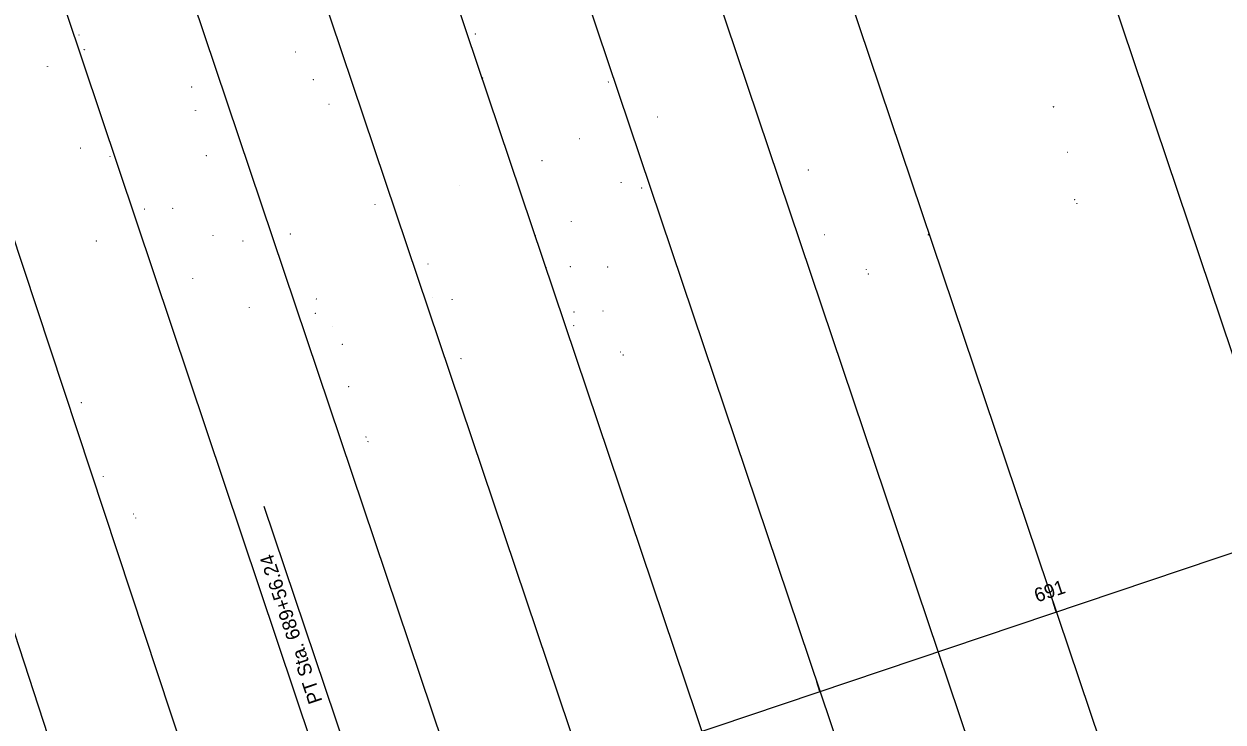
# Model space of a CAD drawing. Extents: x 2175772 to 2185556, y 721391 to 722853.
# Drawn here: x 2178626.6 to 2178867, y 721714.1 to 721854.1 of the extents above; entities that cross this region are included whole.
import ezdxf

# ---------------------------------------------------------------- set-up
doc = ezdxf.new("R2010")
doc.units = 0
for name, color, linetype in [('DT_X_Triangles', 7, 'Continuous'), ('RD_X_Cells', 7, 'Continuous'), ('SV_X_Shot_Marker', 7, 'Continuous'), ('SV_X_Text_Comment', 7, 'Continuous'), ('SV_X_Text_Description', 7, 'Continuous')]:
    doc.layers.add(name, color=color, linetype=linetype)

msp = doc.modelspace()

# ---------------------------------------------------------------- linework, layer by layer
at = {"layer": 'DT_X_Triangles'}
for p, q in [((2178697.33, 721690.31), (2180444.45, 722278.43)), ((2178697.01, 721691.26), (2178674.76, 721757.36)), ((2178833.58, 721736.18), (2178832.94, 721738.07)), ((2178786.19, 721720.22), (2178785.55, 721722.12))]:
    msp.add_line(p, q, dxfattribs=at)
at = {"layer": 'RD_X_Cells'}
for p, q in [((2178717.04, 721852.07), (2178717.1, 721852.13)), ((2178717.04, 721852.13), (2178717.1, 721852.07)), ((2178717.04, 721852.07), (2178717.1, 721852.13)), ((2178717.04, 721852.13), (2178717.1, 721852.07)), ((2178638.67, 721848.98), (2178638.74, 721849.05)), ((2178638.67, 721849.05), (2178638.74, 721848.98)), ((2178638.67, 721848.98), (2178638.74, 721849.05)), ((2178638.67, 721849.05), (2178638.74, 721848.98)), ((2178681.04, 721848.52), (2178681.1, 721848.58)), ((2178681.04, 721848.58), (2178681.1, 721848.52)), ((2178681.04, 721848.52), (2178681.1, 721848.58)), ((2178681.04, 721848.58), (2178681.1, 721848.52)), ((2178684.57, 721842.93), (2178684.64, 721843)), ((2178684.57, 721843), (2178684.64, 721842.93)), ((2178684.57, 721842.93), (2178684.64, 721843)), ((2178684.57, 721843), (2178684.64, 721842.93)), ((2178718.5, 721843.24), (2178718.57, 721843.31)), ((2178718.5, 721843.31), (2178718.57, 721843.24)), ((2178718.5, 721843.24), (2178718.57, 721843.31)), ((2178718.5, 721843.31), (2178718.57, 721843.24)), ((2178660.15, 721841.45), (2178660.22, 721841.52)), ((2178660.15, 721841.52), (2178660.22, 721841.45)), ((2178660.15, 721841.45), (2178660.22, 721841.52)), ((2178660.15, 721841.52), (2178660.22, 721841.45)), ((2178660.94, 721836.71), (2178661, 721836.78)), ((2178660.94, 721836.78), (2178661, 721836.71)), ((2178660.94, 721836.71), (2178661, 721836.78)), ((2178660.94, 721836.78), (2178661, 721836.71)), ((2178687.73, 721838.02), (2178687.8, 721838.08)), ((2178687.73, 721838.08), (2178687.8, 721838.02)), ((2178687.73, 721838.02), (2178687.8, 721838.08)), ((2178687.73, 721838.08), (2178687.8, 721838.02)), ((2178832.99, 721837.53), (2178833.06, 721837.6)), ((2178832.99, 721837.6), (2178833.06, 721837.53)), ((2178832.99, 721837.53), (2178833.06, 721837.6)), ((2178832.99, 721837.6), (2178833.06, 721837.53)), ((2178663.1, 721827.71), (2178663.17, 721827.77)), ((2178663.1, 721827.77), (2178663.17, 721827.71)), ((2178663.1, 721827.71), (2178663.17, 721827.77)), ((2178663.1, 721827.77), (2178663.17, 721827.71)), ((2178783.8, 721824.8), (2178783.87, 721824.87)), ((2178783.8, 721824.87), (2178783.87, 721824.8)), ((2178783.8, 721824.8), (2178783.87, 721824.87)), ((2178783.8, 721824.87), (2178783.87, 721824.8)), ((2178641.05, 721810.58), (2178641.12, 721810.65)), ((2178641.05, 721810.65), (2178641.12, 721810.58)), ((2178641.05, 721810.58), (2178641.12, 721810.65)), ((2178641.05, 721810.65), (2178641.12, 721810.58)), ((2178736.1, 721805.41), (2178736.17, 721805.48)), ((2178736.1, 721805.48), (2178736.17, 721805.41)), ((2178736.1, 721805.41), (2178736.17, 721805.48)), ((2178736.1, 721805.48), (2178736.17, 721805.41)), ((2178712.41, 721798.78), (2178712.47, 721798.85)), ((2178712.41, 721798.85), (2178712.47, 721798.78)), ((2178712.41, 721798.78), (2178712.47, 721798.85)), ((2178712.41, 721798.85), (2178712.47, 721798.78)), ((2178736.86, 721796.33), (2178736.93, 721796.4)), ((2178736.86, 721796.4), (2178736.93, 721796.33)), ((2178736.86, 721796.33), (2178736.93, 721796.4)), ((2178736.86, 721796.4), (2178736.93, 721796.33)), ((2178690.38, 721789.84), (2178690.44, 721789.91)), ((2178690.38, 721789.91), (2178690.44, 721789.84)), ((2178690.38, 721789.84), (2178690.44, 721789.91)), ((2178690.38, 721789.91), (2178690.44, 721789.84)), ((2178638.07, 721778.14), (2178638.14, 721778.21)), ((2178638.07, 721778.21), (2178638.14, 721778.14)), ((2178638.07, 721778.14), (2178638.14, 721778.21)), ((2178638.07, 721778.21), (2178638.14, 721778.14))]:
    msp.add_line(p, q, dxfattribs=at)
at = {"layer": 'SV_X_Shot_Marker'}
for points in [[(2178721.45, 722226), (2178912.87, 721657.35)], [(2178674.07, 722210.05), (2178865.48, 721641.4)], [(2178650.37, 722202.07), (2178841.79, 721633.43)], [(2178626.68, 722194.1), (2178818.1, 721625.45)], [(2178602.98, 722186.12), (2178794.4, 721617.47)], [(2178579.29, 722178.15), (2178770.71, 721609.5)], [(2178555.6, 722170.17), (2178747.01, 721601.52)], [(2178532.42, 722162.37), (2178723.22, 721593.52)], [(2178510.77, 722155.16), (2178699.08, 721585.48)], [(2178489.09, 722148.05), (2178674.91, 721577.55)]]:
    msp.add_lwpolyline(points, dxfattribs=at)
at = {"layer": 'SV_X_Text_Comment'}
for p, q in [((2178637.62, 721851.87), (2178637.58, 721851.91)), ((2178637.62, 721851.91), (2178637.58, 721851.87)), ((2178637.62, 721851.87), (2178637.58, 721851.91)), ((2178637.62, 721851.91), (2178637.58, 721851.87)), ((2178637.6, 721851.89), (2178637.6, 721851.89)), ((2178637.6, 721851.89), (2178637.6, 721851.89)), ((2178631.31, 721845.63), (2178631.27, 721845.66)), ((2178631.31, 721845.66), (2178631.27, 721845.63)), ((2178631.31, 721845.63), (2178631.27, 721845.66)), ((2178631.31, 721845.66), (2178631.27, 721845.63)), ((2178631.29, 721845.65), (2178631.29, 721845.65)), ((2178631.29, 721845.65), (2178631.29, 721845.65)), ((2178743.77, 721842.48), (2178743.72, 721842.49)), ((2178743.77, 721842.48), (2178743.72, 721842.49)), ((2178743.76, 721842.51), (2178743.74, 721842.46)), ((2178743.76, 721842.51), (2178743.74, 721842.46)), ((2178743.75, 721842.48), (2178743.75, 721842.48)), ((2178743.75, 721842.48), (2178743.75, 721842.48)), ((2178753.55, 721835.52), (2178753.59, 721835.5)), ((2178753.55, 721835.52), (2178753.59, 721835.5)), ((2178753.56, 721835.49), (2178753.58, 721835.53)), ((2178753.56, 721835.49), (2178753.58, 721835.53)), ((2178753.57, 721835.51), (2178753.57, 721835.51)), ((2178753.57, 721835.51), (2178753.57, 721835.51)), ((2178738.04, 721831.08), (2178738, 721831.1)), ((2178738.04, 721831.08), (2178738, 721831.1)), ((2178738.03, 721831.12), (2178738.01, 721831.07)), ((2178738.03, 721831.12), (2178738.01, 721831.07)), ((2178738.02, 721831.09), (2178738.02, 721831.09)), ((2178738.02, 721831.09), (2178738.02, 721831.09)), ((2178637.89, 721829.24), (2178637.86, 721829.21)), ((2178637.86, 721829.24), (2178637.89, 721829.21)), ((2178637.89, 721829.24), (2178637.86, 721829.21)), ((2178637.86, 721829.24), (2178637.89, 721829.21)), ((2178637.88, 721829.23), (2178637.88, 721829.23)), ((2178637.88, 721829.23), (2178637.88, 721829.23)), ((2178643.83, 721827.49), (2178643.86, 721827.53)), ((2178643.86, 721827.5), (2178643.83, 721827.53)), ((2178643.83, 721827.49), (2178643.86, 721827.53)), ((2178643.86, 721827.5), (2178643.83, 721827.53)), ((2178643.84, 721827.51), (2178643.84, 721827.51)), ((2178643.84, 721827.51), (2178643.84, 721827.51)), ((2178730.48, 721826.72), (2178730.44, 721826.7)), ((2178730.48, 721826.72), (2178730.44, 721826.7)), ((2178730.47, 721826.69), (2178730.45, 721826.73)), ((2178730.47, 721826.69), (2178730.45, 721826.73)), ((2178730.46, 721826.71), (2178730.46, 721826.71)), ((2178730.46, 721826.71), (2178730.46, 721826.71)), ((2178835.9, 721828.36), (2178835.86, 721828.35)), ((2178835.9, 721828.36), (2178835.86, 721828.35)), ((2178835.89, 721828.33), (2178835.87, 721828.38)), ((2178835.89, 721828.33), (2178835.87, 721828.38)), ((2178835.88, 721828.35), (2178835.88, 721828.35)), ((2178835.88, 721828.35), (2178835.88, 721828.35)), ((2178714.01, 721821.82), (2178713.96, 721821.8)), ((2178714.01, 721821.82), (2178713.96, 721821.8)), ((2178713.99, 721821.79), (2178713.98, 721821.83)), ((2178713.99, 721821.79), (2178713.98, 721821.83)), ((2178713.98, 721821.81), (2178713.98, 721821.81)), ((2178713.98, 721821.81), (2178713.98, 721821.81)), ((2178746.3, 721822.3), (2178746.33, 721822.27)), ((2178746.3, 721822.27), (2178746.34, 721822.3)), ((2178746.3, 721822.3), (2178746.33, 721822.27)), ((2178746.3, 721822.27), (2178746.34, 721822.3)), ((2178746.32, 721822.29), (2178746.32, 721822.29)), ((2178746.32, 721822.29), (2178746.32, 721822.29)), ((2178750.36, 721821.23), (2178750.41, 721821.23)), ((2178750.36, 721821.23), (2178750.41, 721821.23)), ((2178750.38, 721821.25), (2178750.38, 721821.2)), ((2178750.38, 721821.25), (2178750.38, 721821.2)), ((2178750.38, 721821.23), (2178750.38, 721821.23)), ((2178750.38, 721821.23), (2178750.38, 721821.23)), ((2178837.2, 721818.93), (2178837.25, 721818.94)), ((2178837.2, 721818.93), (2178837.25, 721818.94)), ((2178837.22, 721818.96), (2178837.23, 721818.91)), ((2178837.22, 721818.96), (2178837.23, 721818.91)), ((2178837.22, 721818.94), (2178837.22, 721818.94)), ((2178837.22, 721818.94), (2178837.22, 721818.94)), ((2178650.72, 721817), (2178650.69, 721816.96)), ((2178650.69, 721817), (2178650.72, 721816.96)), ((2178650.72, 721817), (2178650.69, 721816.96)), ((2178650.69, 721817), (2178650.72, 721816.96)), ((2178650.71, 721816.98), (2178650.71, 721816.98)), ((2178650.71, 721816.98), (2178650.71, 721816.98)), ((2178656.43, 721817.12), (2178656.39, 721817.15)), ((2178656.43, 721817.12), (2178656.39, 721817.15)), ((2178656.4, 721817.11), (2178656.43, 721817.15)), ((2178656.4, 721817.11), (2178656.43, 721817.15)), ((2178656.41, 721817.13), (2178656.41, 721817.13)), ((2178656.41, 721817.13), (2178656.41, 721817.13)), ((2178697.02, 721817.95), (2178696.97, 721817.94)), ((2178697.02, 721817.95), (2178696.97, 721817.94)), ((2178697, 721817.92), (2178696.99, 721817.97)), ((2178697, 721817.92), (2178696.99, 721817.97)), ((2178697, 721817.94), (2178697, 721817.94)), ((2178697, 721817.94), (2178697, 721817.94)), ((2178837.69, 721818.15), (2178837.73, 721818.17)), ((2178837.69, 721818.15), (2178837.73, 721818.17)), ((2178837.7, 721818.18), (2178837.72, 721818.14)), ((2178837.7, 721818.18), (2178837.72, 721818.14)), ((2178837.71, 721818.16), (2178837.71, 721818.16)), ((2178837.71, 721818.16), (2178837.71, 721818.16)), ((2178736.29, 721814.52), (2178736.33, 721814.54)), ((2178736.29, 721814.52), (2178736.33, 721814.54)), ((2178736.3, 721814.55), (2178736.32, 721814.51)), ((2178736.3, 721814.55), (2178736.32, 721814.51)), ((2178736.31, 721814.53), (2178736.31, 721814.53)), ((2178736.31, 721814.53), (2178736.31, 721814.53)), ((2178680, 721812), (2178679.95, 721811.98)), ((2178680, 721812), (2178679.95, 721811.98)), ((2178679.99, 721811.97), (2178679.97, 721812.01)), ((2178679.99, 721811.97), (2178679.97, 721812.01)), ((2178679.98, 721811.99), (2178679.98, 721811.99)), ((2178679.98, 721811.99), (2178679.98, 721811.99)), ((2178787.18, 721811.84), (2178787.13, 721811.82)), ((2178787.18, 721811.84), (2178787.13, 721811.82)), ((2178787.17, 721811.81), (2178787.15, 721811.86)), ((2178787.17, 721811.81), (2178787.15, 721811.86)), ((2178787.16, 721811.83), (2178787.16, 721811.83)), ((2178787.16, 721811.83), (2178787.16, 721811.83)), ((2178664.54, 721811.67), (2178664.49, 721811.68)), ((2178664.54, 721811.67), (2178664.49, 721811.68)), ((2178664.51, 721811.65), (2178664.52, 721811.7)), ((2178664.51, 721811.65), (2178664.52, 721811.7)), ((2178664.52, 721811.67), (2178664.52, 721811.67)), ((2178664.52, 721811.67), (2178664.52, 721811.67)), ((2178670.48, 721810.6), (2178670.43, 721810.59)), ((2178670.48, 721810.6), (2178670.43, 721810.59)), ((2178670.46, 721810.57), (2178670.45, 721810.62)), ((2178670.46, 721810.57), (2178670.45, 721810.62)), ((2178670.45, 721810.59), (2178670.45, 721810.59)), ((2178670.45, 721810.59), (2178670.45, 721810.59)), ((2178729.04, 721811.67), (2178729.09, 721811.68)), ((2178729.04, 721811.67), (2178729.09, 721811.68)), ((2178729.06, 721811.7), (2178729.07, 721811.65)), ((2178729.06, 721811.7), (2178729.07, 721811.65)), ((2178729.07, 721811.67), (2178729.07, 721811.67)), ((2178729.07, 721811.67), (2178729.07, 721811.67)), ((2178707.56, 721806.01), (2178707.61, 721806.02)), ((2178707.56, 721806.01), (2178707.61, 721806.02)), ((2178707.58, 721806.04), (2178707.6, 721805.99)), ((2178707.58, 721806.04), (2178707.6, 721805.99)), ((2178707.59, 721806.02), (2178707.59, 721806.02)), ((2178707.59, 721806.02), (2178707.59, 721806.02)), ((2178731.18, 721805.32), (2178731.23, 721805.33)), ((2178731.18, 721805.32), (2178731.23, 721805.33)), ((2178731.2, 721805.35), (2178731.22, 721805.3)), ((2178731.2, 721805.35), (2178731.22, 721805.3)), ((2178731.21, 721805.33), (2178731.21, 721805.33)), ((2178731.21, 721805.33), (2178731.21, 721805.33)), ((2178743.59, 721805.4), (2178743.64, 721805.4)), ((2178743.59, 721805.4), (2178743.64, 721805.4)), ((2178743.61, 721805.42), (2178743.61, 721805.37)), ((2178743.61, 721805.42), (2178743.61, 721805.37)), ((2178743.61, 721805.4), (2178743.61, 721805.4)), ((2178743.61, 721805.4), (2178743.61, 721805.4)), ((2178795.43, 721804.85), (2178795.48, 721804.87)), ((2178795.43, 721804.85), (2178795.48, 721804.87)), ((2178795.45, 721804.88), (2178795.46, 721804.83)), ((2178795.45, 721804.88), (2178795.46, 721804.83)), ((2178795.46, 721804.86), (2178795.46, 721804.86)), ((2178795.46, 721804.86), (2178795.46, 721804.86)), ((2178660.4, 721803.1), (2178660.36, 721803.07)), ((2178660.4, 721803.1), (2178660.36, 721803.07)), ((2178660.37, 721803.11), (2178660.39, 721803.06)), ((2178660.37, 721803.11), (2178660.39, 721803.06)), ((2178660.38, 721803.08), (2178660.38, 721803.08)), ((2178660.38, 721803.08), (2178660.38, 721803.08)), ((2178795.85, 721803.99), (2178795.9, 721804)), ((2178795.85, 721803.99), (2178795.9, 721804)), ((2178795.87, 721804.02), (2178795.89, 721803.97)), ((2178795.87, 721804.02), (2178795.89, 721803.97)), ((2178795.88, 721803.99), (2178795.88, 721803.99)), ((2178795.88, 721803.99), (2178795.88, 721803.99)), ((2178685.18, 721798.97), (2178685.23, 721798.98)), ((2178685.18, 721798.97), (2178685.23, 721798.98)), ((2178685.2, 721799), (2178685.21, 721798.95)), ((2178685.2, 721799), (2178685.21, 721798.95)), ((2178685.21, 721798.97), (2178685.21, 721798.97)), ((2178685.21, 721798.97), (2178685.21, 721798.97)), ((2178708.54, 721799.25), (2178708.59, 721799.27)), ((2178708.54, 721799.25), (2178708.59, 721799.27)), ((2178708.56, 721799.28), (2178708.57, 721799.24)), ((2178708.56, 721799.28), (2178708.57, 721799.24)), ((2178708.57, 721799.26), (2178708.57, 721799.26)), ((2178708.57, 721799.26), (2178708.57, 721799.26)), ((2178671.71, 721797.25), (2178671.75, 721797.23)), ((2178671.71, 721797.25), (2178671.75, 721797.23)), ((2178671.74, 721797.26), (2178671.72, 721797.21)), ((2178671.74, 721797.26), (2178671.72, 721797.21)), ((2178671.73, 721797.24), (2178671.73, 721797.24)), ((2178671.73, 721797.24), (2178671.73, 721797.24)), ((2178685.04, 721796.1), (2178685, 721796.06)), ((2178685, 721796.1), (2178685.04, 721796.07)), ((2178685.04, 721796.1), (2178685, 721796.06)), ((2178685, 721796.1), (2178685.04, 721796.07)), ((2178685.02, 721796.08), (2178685.02, 721796.08)), ((2178685.02, 721796.08), (2178685.02, 721796.08)), ((2178742.72, 721796.54), (2178742.67, 721796.52)), ((2178742.72, 721796.54), (2178742.67, 721796.52)), ((2178742.7, 721796.5), (2178742.69, 721796.55)), ((2178742.7, 721796.5), (2178742.69, 721796.55)), ((2178742.7, 721796.53), (2178742.7, 721796.53)), ((2178742.7, 721796.53), (2178742.7, 721796.53)), ((2178688.45, 721793.39), (2178688.42, 721793.36)), ((2178688.42, 721793.39), (2178688.46, 721793.36)), ((2178688.45, 721793.39), (2178688.42, 721793.36)), ((2178688.42, 721793.39), (2178688.46, 721793.36)), ((2178688.44, 721793.38), (2178688.44, 721793.38)), ((2178688.44, 721793.38), (2178688.44, 721793.38)), ((2178736.84, 721793.62), (2178736.8, 721793.6)), ((2178736.84, 721793.62), (2178736.8, 721793.6)), ((2178736.83, 721793.58), (2178736.81, 721793.63)), ((2178736.83, 721793.58), (2178736.81, 721793.63)), ((2178736.82, 721793.61), (2178736.82, 721793.61)), ((2178736.82, 721793.61), (2178736.82, 721793.61)), ((2178746.22, 721788.35), (2178746.27, 721788.37)), ((2178746.22, 721788.35), (2178746.27, 721788.37)), ((2178746.24, 721788.38), (2178746.26, 721788.34)), ((2178746.24, 721788.38), (2178746.26, 721788.34)), ((2178746.25, 721788.36), (2178746.25, 721788.36)), ((2178746.25, 721788.36), (2178746.25, 721788.36)), ((2178746.68, 721787.73), (2178746.73, 721787.74)), ((2178746.68, 721787.73), (2178746.73, 721787.74)), ((2178746.7, 721787.76), (2178746.72, 721787.71)), ((2178746.7, 721787.76), (2178746.72, 721787.71)), ((2178746.71, 721787.73), (2178746.71, 721787.73)), ((2178746.71, 721787.73), (2178746.71, 721787.73)), ((2178714.26, 721786.99), (2178714.21, 721786.97)), ((2178714.26, 721786.99), (2178714.21, 721786.97)), ((2178714.24, 721786.96), (2178714.23, 721787.01)), ((2178714.24, 721786.96), (2178714.23, 721787.01)), ((2178714.23, 721786.98), (2178714.23, 721786.98)), ((2178714.23, 721786.98), (2178714.23, 721786.98)), ((2178691.73, 721781.37), (2178691.68, 721781.35)), ((2178691.73, 721781.37), (2178691.68, 721781.35)), ((2178691.71, 721781.33), (2178691.7, 721781.38)), ((2178691.71, 721781.33), (2178691.7, 721781.38)), ((2178691.7, 721781.36), (2178691.7, 721781.36)), ((2178691.7, 721781.36), (2178691.7, 721781.36)), ((2178695.12, 721771.27), (2178695.17, 721771.29)), ((2178695.12, 721771.27), (2178695.17, 721771.29)), ((2178695.14, 721771.3), (2178695.15, 721771.26)), ((2178695.14, 721771.3), (2178695.15, 721771.26)), ((2178695.14, 721771.28), (2178695.14, 721771.28)), ((2178695.14, 721771.28), (2178695.14, 721771.28)), ((2178695.52, 721770.32), (2178695.57, 721770.34)), ((2178695.52, 721770.32), (2178695.57, 721770.34)), ((2178695.54, 721770.35), (2178695.55, 721770.3)), ((2178695.54, 721770.35), (2178695.55, 721770.3)), ((2178695.54, 721770.33), (2178695.54, 721770.33)), ((2178695.54, 721770.33), (2178695.54, 721770.33)), ((2178642.54, 721763.33), (2178642.49, 721763.32)), ((2178642.54, 721763.33), (2178642.49, 721763.32)), ((2178642.53, 721763.3), (2178642.51, 721763.35)), ((2178642.53, 721763.3), (2178642.51, 721763.35)), ((2178642.52, 721763.33), (2178642.52, 721763.33)), ((2178642.52, 721763.33), (2178642.52, 721763.33)), ((2178648.54, 721755.86), (2178648.59, 721755.87)), ((2178648.54, 721755.86), (2178648.59, 721755.87)), ((2178648.56, 721755.89), (2178648.57, 721755.84)), ((2178648.56, 721755.89), (2178648.57, 721755.84)), ((2178648.56, 721755.86), (2178648.56, 721755.86)), ((2178648.56, 721755.86), (2178648.56, 721755.86)), ((2178648.93, 721755.03), (2178648.97, 721755.05)), ((2178648.93, 721755.03), (2178648.97, 721755.05)), ((2178648.94, 721755.06), (2178648.96, 721755.02)), ((2178648.94, 721755.06), (2178648.96, 721755.02)), ((2178648.95, 721755.04), (2178648.95, 721755.04)), ((2178648.95, 721755.04), (2178648.95, 721755.04))]:
    msp.add_line(p, q, dxfattribs=at)
at = {"layer": 'SV_X_Text_Description'}
msp.add_lwpolyline([(2178807.86, 721811.81), (2178807.93, 721811.77), (2178807.99, 721811.81), (2178807.99, 721811.88), (2178807.93, 721811.92), (2178807.86, 721811.88), (2178807.86, 721811.81)], dxfattribs=at)
msp.add_lwpolyline([(2178807.86, 721811.81), (2178807.93, 721811.77), (2178807.99, 721811.81), (2178807.99, 721811.88), (2178807.93, 721811.92), (2178807.86, 721811.88), (2178807.86, 721811.81)], dxfattribs=at)

# ---------------------------------------------------------------- texts
at = {"layer": 'DT_X_Triangles'}
for s, rotation, p in [('PT Sta. 689+56.24', 108.6042, (2178686.44, 721718.3)), ('691', 18.6042, (2178829.73, 721738.05))]:
    msp.add_text(s, height=2.8, rotation=rotation, dxfattribs=at).set_placement(p)

doc.saveas('drawing.dxf')
